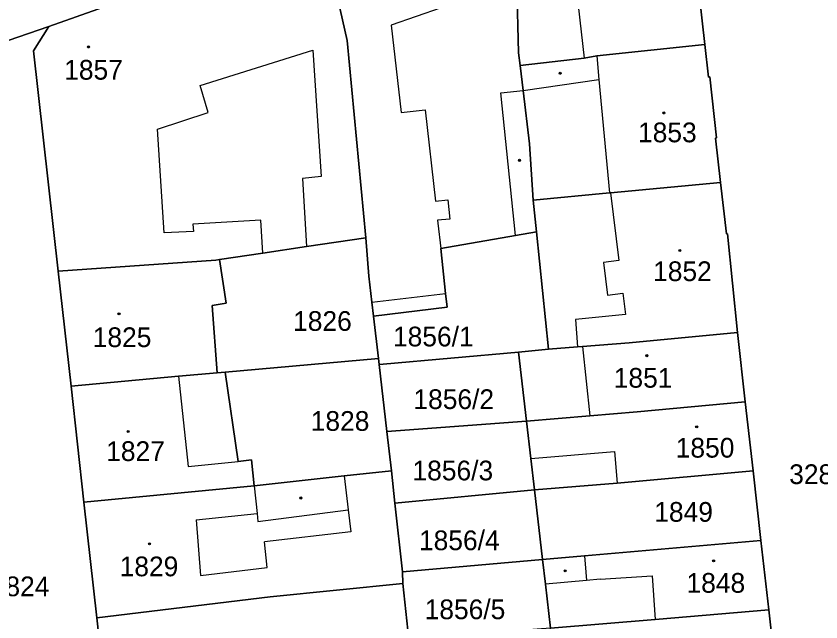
# Model space of a CAD drawing. Extents: x -596233 to -595156, y -1161235 to -1159375.
# Drawn here: x -595847.7 to -595778.3, y -1161202.4 to -1161150.2 of the extents above; entities that cross this region are included whole.
import ezdxf

# ---------------------------------------------------------------- set-up
doc = ezdxf.new("R2010")
doc.units = 0
for name, color, linetype in [('KN_CAR_KR', 7, 'Continuous'), ('KN_KULTURY', 7, 'Continuous'), ('KN_PARC_CIS_POZ', 7, 'Continuous'), ('KN_PARC_CIS_STAV', 7, 'Continuous'), ('KN_PARC_PLOCHA', 7, 'Continuous'), ('parcely_l', 7, 'Continuous')]:
    doc.layers.add(name, color=color, linetype=linetype)

msp = doc.modelspace()

# ---------------------------------------------------------------- linework, layer by layer
at = {"layer": 'KN_CAR_KR'}
for points in [[(-595799.68, -1161145.7), (-595798.76, -1161153.81)], [(-595804.6, -1161147.21), (-595815.39, -1161150.98)], [(-595815.39, -1161150.98), (-595814.51, -1161158.51)], [(-595831.86, -1161156.18), (-595822.14, -1161153.12)], [(-595822.14, -1161153.12), (-595821.42, -1161164.02)], [(-595797.66, -1161153.63), (-595797.47, -1161155.66)], [(-595804.01, -1161156.61), (-595797.47, -1161155.66)], [(-595797.47, -1161155.66), (-595796.56, -1161165.43)], [(-595831.17, -1161158.5), (-595831.86, -1161156.18)], [(-595805.93, -1161156.81), (-595804.01, -1161156.61)], [(-595804.68, -1161169.1), (-595805.93, -1161156.81)], [(-595835.51, -1161159.94), (-595831.17, -1161158.5)], [(-595814.51, -1161158.51), (-595812.44, -1161158.28)], [(-595812.44, -1161158.28), (-595811.57, -1161166.14)], [(-595834.96, -1161168.88), (-595835.51, -1161159.94)], [(-595821.42, -1161164.02), (-595823.04, -1161164.19)], [(-595823.04, -1161164.19), (-595822.68, -1161170.07)], [(-595796.49, -1161165.42), (-595795.76, -1161171.27)], [(-595811.57, -1161166.14), (-595810.51, -1161166.03)], [(-595810.51, -1161166.03), (-595810.33, -1161167.69)], [(-595810.33, -1161167.69), (-595811.38, -1161167.8)], [(-595826.61, -1161167.78), (-595832.48, -1161168.12)], [(-595832.48, -1161168.12), (-595832.41, -1161168.75)], [(-595826.45, -1161170.63), (-595826.61, -1161167.78)], [(-595811.38, -1161167.8), (-595811.36, -1161168.05)], [(-595811.36, -1161168.05), (-595811.11, -1161170.22)], [(-595832.41, -1161168.75), (-595834.96, -1161168.88)], [(-595795.76, -1161171.27), (-595797.08, -1161171.44)], [(-595797.08, -1161171.44), (-595796.73, -1161174.26)], [(-595817.05, -1161174.85), (-595810.69, -1161174.11)], [(-595796.73, -1161174.26), (-595795.41, -1161174.09)], [(-595795.41, -1161174.09), (-595795.18, -1161175.93)], [(-595795.18, -1161175.93), (-595799.5, -1161176.36)], [(-595799.5, -1161176.36), (-595799.32, -1161178.72)], [(-595798.9, -1161178.69), (-595798.27, -1161184.65)], [(-595833.71, -1161181.25), (-595832.89, -1161189.03)], [(-595803.34, -1161188.33), (-595796.13, -1161187.74)], [(-595796.13, -1161187.74), (-595795.89, -1161190.46)], [(-595832.89, -1161189.03), (-595828.56, -1161188.58)], [(-595819.44, -1161189.84), (-595819.1, -1161192.75)], [(-595827.19, -1161190.69), (-595826.94, -1161193.08)], [(-595832.19, -1161193.62), (-595826.94, -1161193.08)], [(-595826.94, -1161193.08), (-595826.87, -1161193.77)], [(-595826.87, -1161193.77), (-595819.1, -1161192.75)], [(-595819.1, -1161192.75), (-595818.87, -1161194.65)], [(-595832.19, -1161193.62), (-595831.81, -1161198.43)], [(-595818.87, -1161194.65), (-595826.29, -1161195.53)], [(-595826.06, -1161197.73), (-595826.29, -1161195.53)], [(-595798.71, -1161196.73), (-595798.61, -1161198.13)], [(-595831.81, -1161198.43), (-595826.06, -1161197.73)], [(-595798.61, -1161198.13), (-595798.56, -1161198.85)], [(-595798.56, -1161198.85), (-595802.09, -1161199.18)], [(-595797.38, -1161198.74), (-595798.56, -1161198.85)], [(-595797.38, -1161198.74), (-595792.9, -1161198.44)], [(-595792.9, -1161198.44), (-595792.63, -1161202.23)]]:
    msp.add_lwpolyline(points, dxfattribs=at)
at = {"layer": 'KN_KULTURY'}
for centre, radius in [((-595841.47, -1161152.85), 0.09), ((-595841.47, -1161152.85), 0.0398), ((-595800.81, -1161155.12), 0.09), ((-595800.81, -1161155.12), 0.0398), ((-595791.88, -1161158.54), 0.09), ((-595791.88, -1161158.54), 0.0398), ((-595804.33, -1161162.63), 0.09), ((-595804.33, -1161162.63), 0.0398), ((-595790.51, -1161170.4), 0.09), ((-595790.51, -1161170.4), 0.0398), ((-595838.84, -1161175.86), 0.09), ((-595838.84, -1161175.86), 0.0398), ((-595793.35, -1161179.47), 0.09), ((-595793.35, -1161179.47), 0.0398), ((-595789.05, -1161185.6), 0.09), ((-595789.05, -1161185.6), 0.0398), ((-595838.06, -1161186), 0.09), ((-595838.06, -1161186), 0.0398), ((-595823.17, -1161191.74), 0.09), ((-595823.17, -1161191.74), 0.0398), ((-595836.21, -1161195.7), 0.09), ((-595836.21, -1161195.7), 0.0398), ((-595787.59, -1161197.16), 0.09), ((-595787.59, -1161197.16), 0.0398), ((-595800.38, -1161198.02), 0.09), ((-595800.38, -1161198.02), 0.0398)]:
    msp.add_circle(centre, radius, dxfattribs=at)
at = {"layer": 'KN_PARC_PLOCHA'}
for points in [[(-595788.34, -1161152.63), (-595797.66, -1161153.63), (-595798.76, -1161153.81), (-595804.27, -1161154.44), (-595804.4, -1161153.35), (-595804.54, -1161147.52), (-595804.6, -1161147.21), (-595806.43, -1161137.5), (-595792.31, -1161132.6), (-595790.48, -1161133.65), (-595789.32, -1161143.93)], [(-595806.43, -1161137.5), (-595804.6, -1161147.21), (-595804.54, -1161147.52), (-595804.4, -1161153.35), (-595804.27, -1161154.44), (-595804.01, -1161156.61), (-595803.46, -1161161.2), (-595803.13, -1161166.05), (-595802.85, -1161168.78), (-595804.68, -1161169.1), (-595811.11, -1161170.22), (-595810.69, -1161174.11), (-595810.55, -1161175.3), (-595816.91, -1161176.05), (-595817.05, -1161174.85), (-595817.31, -1161172.62), (-595817.56, -1161169.3), (-595819.18, -1161152.3), (-595821.33, -1161142.73), (-595806.45, -1161137.45)], [(-595817.56, -1161169.3), (-595822.68, -1161170.07), (-595826.45, -1161170.63), (-595830.17, -1161171.19), (-595830.51, -1161171.24), (-595844.09, -1161172.17), (-595846.2, -1161153.18), (-595844.89, -1161151.09), (-595821.33, -1161142.73), (-595819.18, -1161152.3)], [(-595786.99, -1161164.53), (-595796.49, -1161165.42), (-595796.56, -1161165.43), (-595803.13, -1161166.05), (-595803.46, -1161161.2), (-595804.01, -1161156.61), (-595804.27, -1161154.44), (-595798.76, -1161153.81), (-595797.66, -1161153.63), (-595788.34, -1161152.63), (-595788.02, -1161155.45), (-595787.92, -1161155.44), (-595787.33, -1161160.7), (-595787.43, -1161160.71)], [(-595785.53, -1161177.46), (-595794.88, -1161178.37), (-595798.9, -1161178.69), (-595799.32, -1161178.72), (-595801.81, -1161178.92), (-595802.85, -1161168.78), (-595803.13, -1161166.05), (-595796.56, -1161165.43), (-595796.49, -1161165.42), (-595786.99, -1161164.53), (-595786.49, -1161168.96), (-595786.39, -1161168.95)], [(-595801.81, -1161178.92), (-595804.4, -1161179.16), (-595816.08, -1161180.21), (-595816.42, -1161180.24), (-595816.48, -1161179.72), (-595816.91, -1161176.05), (-595810.55, -1161175.3), (-595810.69, -1161174.11), (-595811.11, -1161170.22), (-595804.68, -1161169.1), (-595802.85, -1161168.78)], [(-595816.91, -1161176.05), (-595816.48, -1161179.72), (-595829.7, -1161180.89), (-595830.37, -1161180.95), (-595830.8, -1161175.13), (-595829.61, -1161174.95), (-595830.17, -1161171.19), (-595826.45, -1161170.63), (-595822.68, -1161170.07), (-595817.56, -1161169.3), (-595817.31, -1161172.62), (-595817.05, -1161174.85)], [(-595830.37, -1161180.95), (-595833.71, -1161181.25), (-595842.98, -1161182.1), (-595844.09, -1161172.17), (-595830.51, -1161171.24), (-595830.17, -1161171.19), (-595829.61, -1161174.95), (-595830.8, -1161175.13)], [(-595784.86, -1161183.44), (-595794.18, -1161184.3), (-595798.27, -1161184.65), (-595803.71, -1161185.12), (-595804.4, -1161179.16), (-595801.81, -1161178.92), (-595799.32, -1161178.72), (-595798.9, -1161178.69), (-595794.88, -1161178.37), (-595785.53, -1161177.46)], [(-595803.71, -1161185.12), (-595815.75, -1161186.01), (-595816.42, -1161180.24), (-595816.08, -1161180.21), (-595804.4, -1161179.16)], [(-595816.42, -1161180.24), (-595815.75, -1161186.01), (-595815.36, -1161189.4), (-595819.44, -1161189.84), (-595827.19, -1161190.69), (-595827.43, -1161188.46), (-595828.56, -1161188.58), (-595829.7, -1161180.89), (-595816.48, -1161179.72)], [(-595827.19, -1161190.69), (-595841.87, -1161192.11), (-595842.98, -1161182.1), (-595833.71, -1161181.25), (-595830.37, -1161180.95), (-595829.7, -1161180.89), (-595828.56, -1161188.58), (-595827.43, -1161188.46)], [(-595784.19, -1161189.41), (-595795.89, -1161190.46), (-595803.03, -1161191.04), (-595803.34, -1161188.33), (-595803.71, -1161185.12), (-595798.27, -1161184.65), (-595794.18, -1161184.3), (-595784.86, -1161183.44)], [(-595803.03, -1161191.04), (-595815.08, -1161192.18), (-595815.36, -1161189.4), (-595815.75, -1161186.01), (-595803.71, -1161185.12), (-595803.34, -1161188.33)], [(-595815.08, -1161192.18), (-595814.42, -1161198.12), (-595814.38, -1161199.11), (-595825.8, -1161200.27), (-595840.76, -1161202.07), (-595841.87, -1161192.11), (-595827.19, -1161190.69), (-595819.44, -1161189.84), (-595815.36, -1161189.4)], [(-595783.51, -1161195.41), (-595798.71, -1161196.73), (-595802.33, -1161197.05), (-595803.03, -1161191.04), (-595795.89, -1161190.46), (-595784.19, -1161189.41)], [(-595802.33, -1161197.05), (-595814.42, -1161198.12), (-595815.08, -1161192.18), (-595803.03, -1161191.04)], [(-595782.83, -1161201.38), (-595792.63, -1161202.23), (-595801.65, -1161202.97), (-595802.09, -1161199.18), (-595802.33, -1161197.05), (-595798.71, -1161196.73), (-595783.51, -1161195.41)], [(-595801.65, -1161202.97), (-595813.86, -1161203.88), (-595813.94, -1161203.14), (-595814.38, -1161199.11), (-595814.42, -1161198.12), (-595802.33, -1161197.05), (-595802.09, -1161199.18)], [(-595813.86, -1161203.88), (-595813.62, -1161206.63), (-595827.6, -1161207.99), (-595830.72, -1161208.3), (-595839.94, -1161209.47), (-595840.76, -1161202.07), (-595825.8, -1161200.27), (-595814.38, -1161199.11), (-595813.94, -1161203.14)], [(-595781.64, -1161211.96), (-595790.97, -1161212.79), (-595791.47, -1161212.83), (-595796.6, -1161213.25), (-595800.44, -1161213.56), (-595800.49, -1161212.03), (-595801.3, -1161205.7), (-595801.65, -1161202.97), (-595792.63, -1161202.23), (-595782.83, -1161201.38)]]:
    msp.add_lwpolyline(points, close=True, dxfattribs=at)
for points in [[(-595821.33, -1161142.73), (-595844.89, -1161151.09), (-595859.02, -1161155.94), (-595863.44, -1161157.5), (-595863.41, -1161157.59), (-595867.78, -1161159.08), (-595867.75, -1161159.15), (-595898.19, -1161169.93), (-595911.86, -1161182.49), (-595914.41, -1161184.63), (-595934.23, -1161191.38), (-595939.65, -1161193.22), (-595942.15, -1161194.43), (-595943.75, -1161195.12), (-595946.35, -1161199.11)], [(-595767.633, -1161235.4174), (-595778.9982, -1161235.4174), (-595779.62, -1161229.88), (-595780.3, -1161223.9), (-595780.96, -1161217.99), (-595781.64, -1161211.96), (-595782.83, -1161201.38), (-595783.51, -1161195.41), (-595784.19, -1161189.41), (-595784.86, -1161183.44), (-595785.53, -1161177.46), (-595786.39, -1161168.95), (-595786.49, -1161168.96), (-595786.99, -1161164.53), (-595787.43, -1161160.71), (-595787.33, -1161160.7), (-595787.92, -1161155.44), (-595788.02, -1161155.45), (-595788.34, -1161152.63), (-595789.32, -1161143.93)], [(-595859.02, -1161155.94), (-595844.89, -1161151.09), (-595846.2, -1161153.18), (-595844.09, -1161172.17), (-595842.98, -1161182.1), (-595841.87, -1161192.11), (-595840.76, -1161202.07), (-595839.94, -1161209.47), (-595839.28, -1161215.37), (-595838.17, -1161225.38), (-595837.62, -1161230.26), (-595837.06, -1161235.28), (-595837.0446, -1161235.4174), (-595848.5027, -1161235.4174)]]:
    msp.add_lwpolyline(points, dxfattribs=at)
at = {"layer": 'parcely_l'}
for points in [[(-595788.34, -1161152.63), (-595789.32, -1161143.93), (-595790.48, -1161133.65), (-595792.31, -1161132.6)], [(-595804.27, -1161154.44), (-595804.4, -1161153.35), (-595804.54, -1161147.52), (-595804.6, -1161147.21), (-595806.43, -1161137.5)], [(-595821.33, -1161142.73), (-595844.89, -1161151.09)], [(-595821.33, -1161142.73), (-595819.18, -1161152.3), (-595817.56, -1161169.3)], [(-595859.02, -1161155.94), (-595844.89, -1161151.09)], [(-595844.89, -1161151.09), (-595846.2, -1161153.18), (-595844.09, -1161172.17)], [(-595804.27, -1161154.44), (-595798.76, -1161153.81), (-595797.66, -1161153.63), (-595788.34, -1161152.63)], [(-595786.99, -1161164.53), (-595787.43, -1161160.71), (-595787.33, -1161160.7), (-595787.92, -1161155.44), (-595788.02, -1161155.45), (-595788.34, -1161152.63)], [(-595803.13, -1161166.05), (-595803.46, -1161161.2), (-595804.01, -1161156.61), (-595804.27, -1161154.44)], [(-595803.13, -1161166.05), (-595796.56, -1161165.43), (-595796.49, -1161165.42), (-595786.99, -1161164.53)], [(-595785.53, -1161177.46), (-595786.39, -1161168.95), (-595786.49, -1161168.96), (-595786.99, -1161164.53)], [(-595802.85, -1161168.78), (-595803.13, -1161166.05)], [(-595816.91, -1161176.05), (-595810.55, -1161175.3), (-595810.69, -1161174.11), (-595811.11, -1161170.22), (-595804.68, -1161169.1), (-595802.85, -1161168.78)], [(-595801.81, -1161178.92), (-595802.85, -1161168.78)], [(-595830.17, -1161171.19), (-595826.45, -1161170.63), (-595822.68, -1161170.07), (-595817.56, -1161169.3)], [(-595817.56, -1161169.3), (-595817.31, -1161172.62), (-595817.05, -1161174.85), (-595816.91, -1161176.05)], [(-595844.09, -1161172.17), (-595830.51, -1161171.24), (-595830.17, -1161171.19)], [(-595830.17, -1161171.19), (-595829.61, -1161174.95), (-595830.8, -1161175.13), (-595830.37, -1161180.95)], [(-595844.09, -1161172.17), (-595842.98, -1161182.1)], [(-595816.48, -1161179.72), (-595816.91, -1161176.05)], [(-595801.81, -1161178.92), (-595799.32, -1161178.72), (-595798.9, -1161178.69), (-595794.88, -1161178.37), (-595785.53, -1161177.46)], [(-595784.86, -1161183.44), (-595785.53, -1161177.46)], [(-595816.42, -1161180.24), (-595816.08, -1161180.21), (-595804.4, -1161179.16)], [(-595804.4, -1161179.16), (-595801.81, -1161178.92)], [(-595804.4, -1161179.16), (-595803.71, -1161185.12)], [(-595816.48, -1161179.72), (-595829.7, -1161180.89)], [(-595816.42, -1161180.24), (-595816.48, -1161179.72)], [(-595829.7, -1161180.89), (-595830.37, -1161180.95)], [(-595829.7, -1161180.89), (-595828.56, -1161188.58), (-595827.43, -1161188.46), (-595827.19, -1161190.69)], [(-595815.75, -1161186.01), (-595816.42, -1161180.24)], [(-595830.37, -1161180.95), (-595833.71, -1161181.25), (-595842.98, -1161182.1)], [(-595842.98, -1161182.1), (-595841.87, -1161192.11)], [(-595784.86, -1161183.44), (-595794.18, -1161184.3), (-595798.27, -1161184.65), (-595803.71, -1161185.12)], [(-595784.19, -1161189.41), (-595784.86, -1161183.44)], [(-595803.71, -1161185.12), (-595815.75, -1161186.01)], [(-595803.03, -1161191.04), (-595803.34, -1161188.33), (-595803.71, -1161185.12)], [(-595815.75, -1161186.01), (-595815.36, -1161189.4)], [(-595827.19, -1161190.69), (-595819.44, -1161189.84), (-595815.36, -1161189.4)], [(-595815.36, -1161189.4), (-595815.08, -1161192.18)], [(-595803.03, -1161191.04), (-595795.89, -1161190.46), (-595784.19, -1161189.41)], [(-595783.51, -1161195.41), (-595784.19, -1161189.41)], [(-595841.87, -1161192.11), (-595827.19, -1161190.69)], [(-595815.08, -1161192.18), (-595803.03, -1161191.04)], [(-595803.03, -1161191.04), (-595802.33, -1161197.05)], [(-595841.87, -1161192.11), (-595840.76, -1161202.07)], [(-595814.42, -1161198.12), (-595815.08, -1161192.18)], [(-595783.51, -1161195.41), (-595798.71, -1161196.73), (-595802.33, -1161197.05)], [(-595782.83, -1161201.38), (-595783.51, -1161195.41)], [(-595802.33, -1161197.05), (-595814.42, -1161198.12)], [(-595802.33, -1161197.05), (-595802.09, -1161199.18), (-595801.65, -1161202.97)], [(-595814.38, -1161199.11), (-595814.42, -1161198.12)], [(-595814.38, -1161199.11), (-595825.8, -1161200.27), (-595840.76, -1161202.07)], [(-595813.86, -1161203.88), (-595813.94, -1161203.14), (-595814.38, -1161199.11)], [(-595801.65, -1161202.97), (-595792.63, -1161202.23), (-595782.83, -1161201.38)], [(-595781.64, -1161211.96), (-595782.83, -1161201.38)], [(-595840.76, -1161202.07), (-595839.94, -1161209.47)]]:
    msp.add_lwpolyline(points, dxfattribs=at)

# ---------------------------------------------------------------- texts
at = {"layer": 'KN_PARC_CIS_POZ'}
for s, p in [('1826', (-595823.8366, -1161177.33)), ('1856/1', (-595815.2266, -1161178.67)), ('1856/2', (-595813.4666, -1161184.07)), ('1828', (-595822.3166, -1161185.95)), ('1856/3', (-595813.5466, -1161190.22)), ('3286', (-595781.0766, -1161190.54)), ('1849', (-595792.7066, -1161193.79)), ('1856/4', (-595812.9866, -1161196.24)), ('1824', (-595849.8966, -1161200.21)), ('1856/5', (-595812.4966, -1161202.19))]:
    msp.add_text(s, height=1.7, dxfattribs=at).set_placement(p)
at = {"layer": 'KN_PARC_CIS_STAV'}
for s, p in [('1857', (-595843.5666, -1161155.67)), ('1853', (-595794.1066, -1161161.07)), ('1852', (-595792.8066, -1161173.04)), ('1825', (-595841.1066, -1161178.73)), ('1851', (-595796.1966, -1161182.23)), ('1827', (-595839.9466, -1161188.55)), ('1850', (-595790.8566, -1161188.26)), ('1829', (-595838.7866, -1161198.49)), ('1848', (-595789.9266, -1161199.91))]:
    msp.add_text(s, height=1.7, dxfattribs=at).set_placement(p)

doc.saveas('drawing.dxf')
